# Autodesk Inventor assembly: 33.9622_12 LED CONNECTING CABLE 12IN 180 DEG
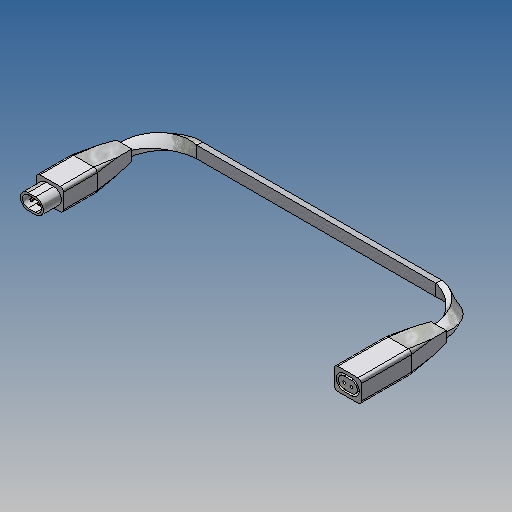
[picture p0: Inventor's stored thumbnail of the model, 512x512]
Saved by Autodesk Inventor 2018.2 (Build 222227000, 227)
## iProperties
Created: 2018-05
Part Number: 33.9622_12 LED CONNECTING CABLE 12IN 180 DEG
Document SubType Name: Assembly
Designer: amoles
Author: amoles
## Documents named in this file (4)
- Y:\INVENTOR LIBRARIES\PARTS LIBRARY\WORKSTATION\LIGHTS OUTWATER PLASTICS\33.9622_12 LED CONNECTING CABLE 12IN 180 DEG.iam
- Y:\INVENTOR LIBRARIES\PARTS LIBRARY\WORKSTATION\LIGHTS OUTWATER PLASTICS\SUBCOMPONENTS\33.9622 PLUG END MALE 90 DEG CORD.ipt
- Y:\INVENTOR LIBRARIES\PARTS LIBRARY\WORKSTATION\LIGHTS OUTWATER PLASTICS\SUBCOMPONENTS\33.9622_12 CORD FOR 180 DEG BEND.ipt
- Y:\INVENTOR LIBRARIES\PARTS LIBRARY\WORKSTATION\LIGHTS OUTWATER PLASTICS\SUBCOMPONENTS\33.9622 PLUG END FEMALE 90 DEG CORD.ipt
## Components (3 placed, 3 different names)
1. 33.9622 PLUG END MALE 90 DEG CORD:1 — Mate:1, Mate:2, Mate:3
2. 33.9622_12 CORD FOR 180 DEG BEND:1 — Mate:1, Mate:2, Mate:3, Mate:4, Mate:5, Mate:6
3. 33.9622 PLUG END FEMALE 90 DEG CORD:1 — Mate:4, Mate:5, Mate:6
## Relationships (6: Mate 6)
- Mate:1: 33.9622 PLUG END MALE 90 DEG CORD:1 ↔ 33.9622_12 CORD FOR 180 DEG BEND:1
- Mate:2: 33.9622 PLUG END MALE 90 DEG CORD:1 ↔ 33.9622_12 CORD FOR 180 DEG BEND:1
- Mate:3: 33.9622 PLUG END MALE 90 DEG CORD:1 ↔ 33.9622_12 CORD FOR 180 DEG BEND:1
- Mate:4: 33.9622_12 CORD FOR 180 DEG BEND:1 ↔ 33.9622 PLUG END FEMALE 90 DEG CORD:1
- Mate:5: 33.9622_12 CORD FOR 180 DEG BEND:1 ↔ 33.9622 PLUG END FEMALE 90 DEG CORD:1
- Mate:6: 33.9622_12 CORD FOR 180 DEG BEND:1 ↔ 33.9622 PLUG END FEMALE 90 DEG CORD:1
